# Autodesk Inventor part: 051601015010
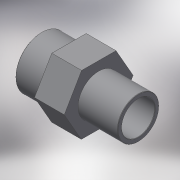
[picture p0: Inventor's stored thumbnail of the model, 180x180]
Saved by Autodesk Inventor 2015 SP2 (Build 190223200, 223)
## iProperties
Created: 2017-10
Part Number: 051601015010
Material: Generic
Description: PLASSON THR. REDUCING NIPPLE 1"-1.1/2" PVC
Document SubType Name: Modeling
Designer: KIM
Density: 1 g/cm^3
Appearance: Default
Author: KIM
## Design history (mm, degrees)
derived "051601.ipt"
feature "Solid1::051601.ipt"
tag "TaggingFeature1"
body "Solid1"
other parameters: "d0" = 56, "d13" = 0, "d14" = 0.33249, "d17" = 22, "d18" = 26.4, "d19" = 47.803, "d21" = 33.249, "d23" = 38.2424, "d24" = 26.5992, "d25" = 22, "d26" = -22, "R_1" = 33.249, "lt_1" = 22, "lt_" = 22, "H_" = 56, "R_" = 47.803
